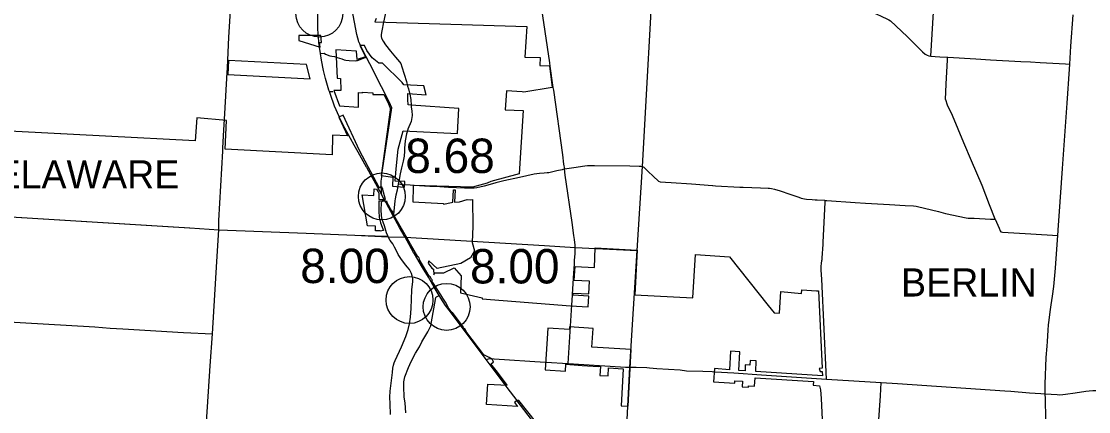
# Model space of a CAD drawing. Extents: x 1597222 to 1925846, y 496284 to 911751.
# Drawn here: x 1799698 to 1833850, y 815408 to 827893 of the extents above; entities that cross this region are included whole.
import ezdxf

# ---------------------------------------------------------------- set-up
doc = ezdxf.new("R2010")
doc.units = 0
for name, color, linetype in [('Default', 7, 'Continuous'), ('GM_X_City_Street', 7, 'Continuous'), ('GM_X_Corporation', 7, 'Continuous'), ('GM_X_County_Road', 7, 'Continuous'), ('GM_X_State_Route', 7, 'Continuous'), ('GM_X_Township', 7, 'Continuous'), ('GM_X_Township_Road', 7, 'Continuous'), ('GM_X_Township_Text', 7, 'Continuous'), ('GM_X_US_Route', 7, 'Continuous')]:
    doc.layers.add(name, color=color, linetype=linetype)

msp = doc.modelspace()

# ---------------------------------------------------------------- linework, layer by layer
at = {"layer": 'Default'}
for centre in [(1809233, 828140), (1811234, 822292), (1812119, 818978), (1813305, 818759)]:
    msp.add_circle(centre, 750, dxfattribs=at)
at = {"layer": 'GM_X_City_Street'}
for points in [[(1810506, 827220), (1810502, 827229), (1810482, 827281), (1810461, 827356), (1810438, 827474), (1810238, 828490), (1810225, 828549), (1810117, 829066), (1810105, 829126), (1810080, 829357), (1810068, 829471), (1810135, 830154), (1810144, 830257), (1810215, 830861), (1810235, 831013), (1810251, 831109), (1810267, 831292), (1810283, 831379)], [(1806208, 824940), (1806284, 826252), (1806292, 826406), (1806341, 827386), (1806384, 828059), (1806393, 828209), (1806439, 829079), (1806485, 829730)], [(1811339, 828131), (1811336, 828114), (1811291, 827864), (1811232, 827586), (1811211, 827467), (1811213, 827409), (1811226, 827353), (1811276, 827254), (1811353, 827144), (1811508, 826935), (1811666, 826747), (1811796, 826596), (1811839, 826549), (1811877, 826439), (1812017, 825974), (1812059, 825816)], [(1809272, 826861), (1809388, 826870), (1809425, 826840), (1809572, 826785), (1809634, 826782), (1809723, 826766), (1809774, 826750)], [(1809554, 825645), (1809661, 825653)], [(1812124, 825562), (1812156, 825394), (1812169, 825198)], [(1812067, 824435), (1812027, 824300), (1811979, 824075), (1811956, 823838), (1811961, 823737), (1811950, 823584), (1811912, 823418), (1811863, 823209), (1811821, 823014), (1811788, 822838)], [(1811218, 822539), (1811212, 822624), (1811214, 822783), (1811229, 822907)], [(1811748, 822631), (1811720, 822495), (1811680, 822334), (1811660, 822220), (1811644, 822150), (1811628, 821928), (1811606, 821726)], [(1812232, 822643), (1812134, 822648), (1811916, 822664)], [(1817270, 818144), (1817313, 818821)], [(1814830, 817099), (1816459, 816996)], [(1818869, 816837), (1819032, 816826), (1819169, 816826), (1819183, 816827)], [(1819183, 816827), (1819368, 816835), (1819716, 816815), (1819794, 816805), (1820031, 816793), (1820776, 816743), (1820982, 816713), (1821507, 816705), (1821800, 816689)]]:
    msp.add_lwpolyline(points, dxfattribs=at)
at = {"layer": 'GM_X_Corporation'}
for points in [[(1811049, 827984), (1811009, 827882), (1815869, 827729), (1815809, 826748), (1816301, 826739), (1816293, 826483), (1816593, 826467), (1816684, 825773), (1815779, 825630), (1815726, 825640), (1815222, 825670), (1815180, 825063), (1815759, 825045), (1815628, 823017), (1814722, 822767), (1814602, 822713), (1814135, 822592), (1812230, 822645), (1812230, 822615), (1812238, 822614), (1812238, 822584), (1812222, 822121), (1813205, 822069), (1813204, 822049), (1813466, 822100), (1813508, 822104), (1813529, 822505), (1813579, 822502), (1813558, 822108), (1813717, 822121), (1813958, 822191), (1814077, 822182), (1814129, 822194), (1814144, 821346), (1814126, 820821), (1814199, 820548), (1814067, 820328), (1813758, 820150), (1813004, 819989), (1812733, 820233), (1812719, 820154), (1812829, 819996), (1812884, 819964), (1812897, 819788), (1812927, 819853), (1813214, 819848), (1813547, 820011), (1813776, 819756), (1813747, 819206), (1814444, 819045), (1814443, 819012), (1817265, 818792), (1817839, 818766), (1817858, 819105), (1817359, 819129), (1817368, 819200), (1817858, 819180), (1817881, 819577), (1817386, 819598), (1817424, 820049), (1818033, 820014), (1818062, 820649), (1819407, 820569), (1819331, 819147), (1821186, 819052), (1821268, 820431), (1822355, 820361), (1823597, 818799), (1823790, 818570), (1823953, 818559), (1824004, 819253), (1824662, 819185), (1824669, 819305), (1825142, 819273), (1825203, 819269), (1825322, 816796), (1825222, 816791), (1825257, 816693), (1825327, 816696), (1825334, 816556), (1823195, 816692), (1823214, 817036), (1823021, 817048), (1823013, 816898), (1822864, 816908), (1822854, 816713), (1822655, 816726), (1822693, 817326), (1822394, 817345), (1822356, 816745), (1821876, 816790), (1821850, 816358), (1822524, 816314), (1822529, 816396), (1822775, 816380), (1822764, 816201), (1822961, 816188), (1822964, 816233), (1823161, 816221), (1823178, 816495), (1825044, 816377), (1825036, 816251), (1825240, 816235), (1825272, 816107), (1825289, 815828), (1825372, 814048)], [(1816155, 815095), (1815617, 815760), (1815561, 815764), (1815479, 815702), (1815572, 815578), (1814586, 815636), (1814625, 816291), (1815246, 816252), (1814939, 816670), (1814720, 816934), (1814753, 816955), (1814811, 816988), (1814776, 817076), (1814667, 817139), (1814496, 817226), (1813955, 817945), (1813903, 818031), (1813839, 818093), (1813831, 818102), (1813843, 818112), (1813482, 818591), (1813470, 818581), (1813351, 818740), (1813288, 818875), (1813189, 819034), (1813124, 819146), (1812881, 819505), (1812836, 819583), (1812849, 819591), (1812841, 819604), (1812840, 819626), (1812822, 819647), (1812774, 819718), (1812742, 819743), (1812429, 820284), (1812442, 820292), (1812415, 820338), (1812417, 820354), (1812400, 820364), (1812387, 820356), (1812151, 820764), (1812047, 820960), (1811983, 821059), (1811619, 821689), (1811632, 821697), (1811579, 821781), (1811582, 821822), (1811562, 821811), (1811560, 821797), (1811397, 822105), (1811403, 822125), (1811382, 822132), (1811133, 822137), (1811133, 821868), (1811134, 821801), (1811137, 821758), (1811143, 821693), (1811151, 821634), (1811163, 821568), (1811177, 821507), (1811194, 821445), (1811208, 821399), (1811222, 821359), (1811281, 821198), (1811184, 821182), (1811183, 821194), (1811026, 821197), (1811031, 821344), (1810779, 821357), (1810605, 822346), (1810980, 822327), (1810984, 822534), (1811067, 822528), (1811119, 822437), (1811132, 822394), (1811132, 822197), (1811349, 822193), (1811259, 822541), (1811249, 822540), (1811248, 822594), (1811168, 822593), (1811175, 822563), (1811162, 822555), (1810518, 823765), (1809997, 824891), (1809861, 824827), (1810131, 824227), (1809651, 824252), (1809640, 823625), (1806224, 823803), (1806265, 824722), (1805316, 824805), (1805265, 824074), (1796641, 824518)]]:
    msp.add_lwpolyline(points, dxfattribs=at)
for points in [[(1808579, 827440), (1808580, 827277), (1809256, 827069), (1809243, 827216), (1809303, 827211), (1809278, 827445)], [(1810680, 827120), (1810555, 827125), (1810531, 827123), (1810705, 826759), (1810448, 826674), (1810424, 826940), (1809760, 826986), (1809802, 826080), (1809910, 826070), (1809921, 825683), (1809702, 825683), (1809880, 825193), (1810482, 825151), (1810482, 825622), (1810610, 825608), (1810614, 825626), (1810943, 825609), (1810942, 825555), (1811292, 825549), (1811441, 825259), (1811467, 825200), (1811504, 825116), (1811497, 825064), (1811212, 822957), (1811584, 822905), (1811579, 822626), (1811958, 822592), (1811972, 822769), (1811662, 822777), (1811687, 823176), (1811759, 823803), (1811913, 824395), (1813652, 824301), (1813695, 825106), (1812168, 825213), (1812072, 825227), (1812064, 825391), (1812060, 825586), (1812655, 825545), (1812574, 825827), (1811933, 825865), (1811884, 825933), (1811257, 826553), (1811133, 826557), (1810925, 826731), (1810749, 826965)], [(1806310, 826192), (1808940, 826058), (1808827, 826510), (1806327, 826644)], [(1816458, 816743), (1817110, 816700), (1817124, 816923), (1817642, 816889), (1818164, 816853), (1818164, 816858), (1818165, 816858), (1818225, 816854), (1818211, 816566), (1818471, 816549), (1818489, 816810), (1818956, 816777), (1818886, 815593), (1819113, 815579), (1819207, 817399), (1817955, 817469), (1817994, 818067), (1817238, 818118), (1817233, 818032), (1816544, 818075)]]:
    msp.add_lwpolyline(points, close=True, dxfattribs=at)
at = {"layer": 'GM_X_County_Road'}
for points in [[(1815650, 832818), (1815681, 832754), (1815696, 832701), (1815707, 832636), (1815724, 832514), (1815839, 831685), (1815910, 831182), (1815924, 831087), (1815997, 830585), (1816596, 826570), (1816611, 826462)], [(1832476, 815177), (1832464, 815817), (1832460, 815979), (1832454, 816292), (1832494, 817138), (1832523, 817499), (1832533, 817655), (1832557, 818019), (1832570, 818189), (1832583, 818334), (1832618, 818604), (1832651, 818829), (1832693, 819102), (1832736, 819407), (1832789, 819993), (1832829, 820607), (1832863, 821044), (1832886, 821374), (1832904, 821666), (1833012, 823190), (1833063, 823927), (1833158, 825274), (1833233, 826364), (1833244, 826526), (1833284, 827097), (1833354, 828099)], [(1810530, 827173), (1810506, 827220)], [(1811229, 822907), (1811238, 822991), (1811547, 825057), (1811556, 825124), (1811513, 825220), (1811486, 825280), (1811221, 825797), (1811181, 825876), (1810967, 826310), (1810735, 826755), (1810555, 827125), (1810530, 827173)], [(1816611, 826462), (1816709, 825776), (1816721, 825692)], [(1816721, 825692), (1817014, 823620), (1817048, 823324), (1817073, 823174), (1817376, 823219), (1817730, 823275), (1817816, 823287), (1818034, 823286), (1819167, 823275), (1819464, 823265), (1819525, 823263), (1819568, 823254)], [(1806145, 823736), (1806150, 823836), (1806167, 824235), (1806208, 824940)], [(1806012, 821223), (1806020, 821521), (1806145, 823736)], [(1819568, 823254), (1819571, 823253), (1819619, 823227), (1819753, 823095), (1819916, 822937), (1820089, 822781), (1820144, 822756), (1820314, 822745), (1820495, 822735), (1821138, 822696), (1821809, 822641), (1821822, 822641), (1821912, 822636), (1822690, 822592), (1822708, 822591), (1822793, 822586), (1823349, 822572), (1823598, 822559), (1823641, 822554), (1823701, 822546), (1823794, 822525), (1823833, 822514), (1823943, 822480), (1824317, 822351), (1824572, 822264), (1824650, 822239), (1824703, 822223), (1824754, 822212), (1824817, 822203), (1825000, 822190), (1825095, 822188), (1825160, 822183)], [(1811226, 822434), (1811220, 822504), (1811218, 822539)], [(1811235, 822329), (1811226, 822434)], [(1825160, 822183), (1825395, 822168), (1825420, 822166), (1825468, 822164), (1826380, 822102), (1826713, 822081), (1827481, 822035), (1827979, 822005), (1828241, 821988), (1828328, 821980), (1828376, 821970), (1829043, 821807), (1829269, 821745), (1829930, 821604), (1829991, 821596), (1830183, 821593), (1830707, 821568), (1830861, 821562), (1830987, 821277), (1831021, 821195), (1831043, 821164), (1831094, 821154), (1832000, 821097), (1832863, 821044)], [(1825464, 816451), (1825308, 819646), (1825294, 819934), (1825289, 820059), (1825298, 820149), (1825316, 820244), (1825321, 820280), (1825325, 820329), (1825352, 820760), (1825357, 820824), (1825422, 822106), (1825420, 822166)], [(1805585, 814578), (1805737, 816876), (1805812, 817899), (1805957, 820207), (1806012, 821223)], [(1814573, 817073), (1814690, 817108), (1814830, 817099)], [(1816459, 816996), (1816476, 816995), (1817194, 816947), (1818869, 816837)], [(1821800, 816689), (1821867, 816685), (1821902, 816683), (1822499, 816646), (1823384, 816589), (1825464, 816451)], [(1825464, 816451), (1827210, 816341), (1827734, 816305), (1831166, 816072), (1831357, 816058), (1831958, 816015)], [(1831958, 816015), (1832323, 815989), (1832460, 815979), (1832837, 815953), (1832930, 815950), (1833024, 815953), (1833112, 815962), (1833413, 816008), (1833762, 816064), (1833870, 816076), (1833979, 816082), (1834125, 816080), (1834617, 816051), (1834676, 816048), (1834735, 816046), (1835535, 816000), (1836888, 815933), (1838141, 815859), (1838366, 815848), (1838544, 815828), (1839093, 815806), (1839372, 815780)]]:
    msp.add_lwpolyline(points, dxfattribs=at)
at = {"layer": 'GM_X_State_Route'}
for points in [[(1811447, 820981), (1811439, 820998), (1811426, 821030), (1811387, 821129), (1811315, 821347), (1811248, 821559), (1811221, 821676), (1811215, 821879), (1811220, 822066), (1811226, 822091)], [(1811226, 822091), (1811226, 822093), (1811237, 822121), (1811244, 822133)], [(1811244, 822133), (1811248, 822139), (1811271, 822169), (1811307, 822197)], [(1811513, 815320), (1811494, 815653), (1811493, 815874), (1811500, 816058), (1811569, 816658), (1811588, 816798), (1811608, 816893), (1811627, 816965), (1811662, 817048), (1811862, 817482), (1812003, 817815), (1812048, 817938), (1812078, 818035), (1812115, 818218), (1812145, 818431), (1812171, 818711), (1812195, 819301), (1812222, 819571), (1812222, 819672), (1812205, 819749), (1812182, 819828), (1812152, 819889), (1812117, 819951), (1812041, 820044), (1811961, 820146), (1811840, 820303), (1811759, 820430), (1811689, 820570), (1811636, 820673), (1811584, 820775), (1811498, 820885), (1811447, 820981)]]:
    msp.add_lwpolyline(points, dxfattribs=at)
at = {"layer": 'GM_X_Township'}
for points in [[(1818966, 812859), (1819169, 816826), (1819403, 820562), (1819571, 823253), (1819973, 830336), (1820000, 830812), (1820182, 834021), (1820873, 833984), (1824840, 833781), (1824931, 833776), (1825545, 833759), (1825602, 833752), (1827748, 833636), (1831529, 833453), (1832327, 833414), (1835297, 833263)], [(1797959, 821729), (1805087, 821285), (1806012, 821223), (1808814, 821113), (1810371, 821058), (1811439, 820998), (1811977, 820984), (1816437, 820719), (1817422, 820661), (1819403, 820562)]]:
    msp.add_lwpolyline(points, dxfattribs=at)
at = {"layer": 'GM_X_Township_Road'}
for points in [[(1828797, 826781), (1828889, 828182), (1828892, 828243), (1829101, 831483), (1829126, 831863), (1829142, 832016)], [(1824755, 828908), (1824759, 828906), (1824806, 828881), (1824854, 828855), (1824865, 828850), (1825377, 828604), (1825454, 828567), (1825926, 828329), (1825999, 828292), (1826685, 828268), (1826777, 828264), (1827111, 828106), (1827169, 828078), (1827454, 827939), (1827508, 827913), (1828046, 827407), (1828188, 827254), (1828471, 826984), (1828536, 826919), (1828620, 826843), (1828679, 826807), (1828738, 826785), (1828797, 826781)], [(1809774, 826750), (1809808, 826739), (1809950, 826691), (1810029, 826662), (1810079, 826649), (1810185, 826637), (1810382, 826632), (1810424, 826636), (1810455, 826644), (1810697, 826732), (1810735, 826755)], [(1828797, 826781), (1828937, 826768), (1829083, 826761), (1829333, 826743), (1829347, 826742)], [(1830861, 821562), (1830675, 822019), (1830437, 822637), (1830098, 823434), (1829858, 824006), (1829489, 824884), (1829338, 825214), (1829276, 825381), (1829272, 825394), (1829293, 825885), (1829337, 826657), (1829333, 826743)], [(1829347, 826742), (1830237, 826689), (1830706, 826659), (1831679, 826611), (1831985, 826593), (1832295, 826575), (1833106, 826529), (1833244, 826526)], [(1812059, 825816), (1812082, 825733), (1812117, 825600), (1812124, 825562)], [(1812169, 825198), (1812173, 825150), (1812194, 825026), (1812201, 824882), (1812171, 824694), (1812069, 824441), (1812067, 824435)], [(1817073, 823174), (1817003, 823145), (1816831, 823109), (1816579, 823050), (1816518, 823043), (1816429, 823038), (1816279, 823027), (1816104, 823009), (1815633, 822894), (1815134, 822786), (1814883, 822730), (1814700, 822678), (1814511, 822622), (1814269, 822570), (1814184, 822554), (1814027, 822554), (1813877, 822560), (1813626, 822567), (1813365, 822580), (1813087, 822600), (1812773, 822614), (1812270, 822641), (1812232, 822643)], [(1817422, 820643), (1817422, 820661), (1817420, 820732), (1817398, 820917), (1817377, 821042), (1817319, 821461), (1817102, 822974), (1817073, 823174)], [(1811788, 822838), (1811759, 822683), (1811748, 822631)], [(1811916, 822664), (1811901, 822665), (1811759, 822683)], [(1797934, 821731), (1797959, 821729), (1805080, 821285)], [(1811606, 821726), (1811600, 821672)], [(1805080, 821285), (1805087, 821285), (1806012, 821223)], [(1806012, 821223), (1806012, 821223), (1808814, 821113), (1810371, 821058), (1811348, 821023), (1811426, 821030)], [(1817313, 818821), (1817322, 818966), (1817346, 819339), (1817376, 819835), (1817397, 820137), (1817400, 820253), (1817417, 820451), (1817422, 820643)], [(1812001, 815365), (1811975, 815685), (1811950, 815872), (1811933, 816216), (1811939, 816364), (1811969, 816517), (1812081, 816818), (1812169, 817011), (1812315, 817277), (1812437, 817486), (1812517, 817636), (1812610, 817797), (1812701, 817964), (1812797, 818152), (1812824, 818279), (1812897, 818699), (1812958, 819056), (1812980, 819079), (1812998, 819090), (1813066, 819123)], [(1797748, 818428), (1797746, 818394), (1798913, 818302), (1802044, 818116), (1802541, 818082), (1802940, 818062), (1804889, 817941), (1805812, 817899)], [(1817194, 816947), (1817270, 818144)], [(1826943, 811293), (1827025, 812853), (1827068, 814151), (1827071, 814228), (1827188, 815919), (1827210, 816341)]]:
    msp.add_lwpolyline(points, dxfattribs=at)
at = {"layer": 'GM_X_US_Route'}
for points in [[(1809185, 827707), (1809181, 827785), (1809185, 828089), (1809185, 828132)], [(1809214, 827282), (1809209, 827339), (1809200, 827447), (1809185, 827707)], [(1809236, 827071), (1809235, 827075), (1809220, 827214), (1809214, 827282)], [(1809539, 825695), (1809427, 826070), (1809364, 826320), (1809297, 826652), (1809272, 826861), (1809236, 827071)], [(1809871, 824842), (1809868, 824846), (1809721, 825180), (1809589, 825557), (1809554, 825645), (1809539, 825695)], [(1810349, 823936), (1810231, 824145), (1810052, 824472), (1809871, 824842)], [(1810745, 823229), (1810480, 823705), (1810349, 823936)], [(1811356, 822110), (1811307, 822197), (1811235, 822329), (1811210, 822389), (1810886, 822980), (1810752, 823218), (1810745, 823229)], [(1811380, 822066), (1811356, 822110)], [(1812274, 820456), (1812250, 820496), (1811977, 820984), (1811799, 821302), (1811600, 821672), (1811380, 822066)], [(1814573, 817073), (1813939, 817914), (1813382, 818649), (1813272, 818802), (1813124, 819034), (1813066, 819123), (1812906, 819393), (1812721, 819714), (1812534, 820020), (1812274, 820456)], [(1815183, 816265), (1814573, 817073)], [(1815247, 816180), (1815183, 816265)], [(1815568, 815755), (1815561, 815764), (1815247, 816180)], [(1818772, 810948), (1818759, 811018), (1818704, 811246), (1818662, 811380), (1818602, 811532), (1818561, 811618), (1818501, 811720), (1818431, 811839), (1818397, 811882), (1818191, 812181), (1818168, 812215), (1817777, 812779), (1817339, 813398), (1816925, 813961), (1816128, 815013), (1815568, 815755)]]:
    msp.add_lwpolyline(points, dxfattribs=at)

# ---------------------------------------------------------------- texts
at = {"layer": 'Default'}
for s, p in [('8.68', (1811984, 823042)), ('8.00', (1808623, 819521)), ('8.00', (1814055, 819509))]:
    msp.add_text(s, height=1100, dxfattribs=at).set_placement(p)
at = {"layer": 'GM_X_Township_Text'}
for s, p in [('DELAWARE', (1798000, 822547)), ('BERLIN', (1827845, 819091))]:
    msp.add_text(s, height=900, rotation=0, dxfattribs=at).set_placement(p)

doc.saveas('drawing.dxf')
